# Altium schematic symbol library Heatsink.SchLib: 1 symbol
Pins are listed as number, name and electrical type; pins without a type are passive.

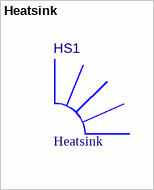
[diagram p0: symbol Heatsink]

## Heatsink
designator HS1
Heatsink Symbol
footprint Heatsink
